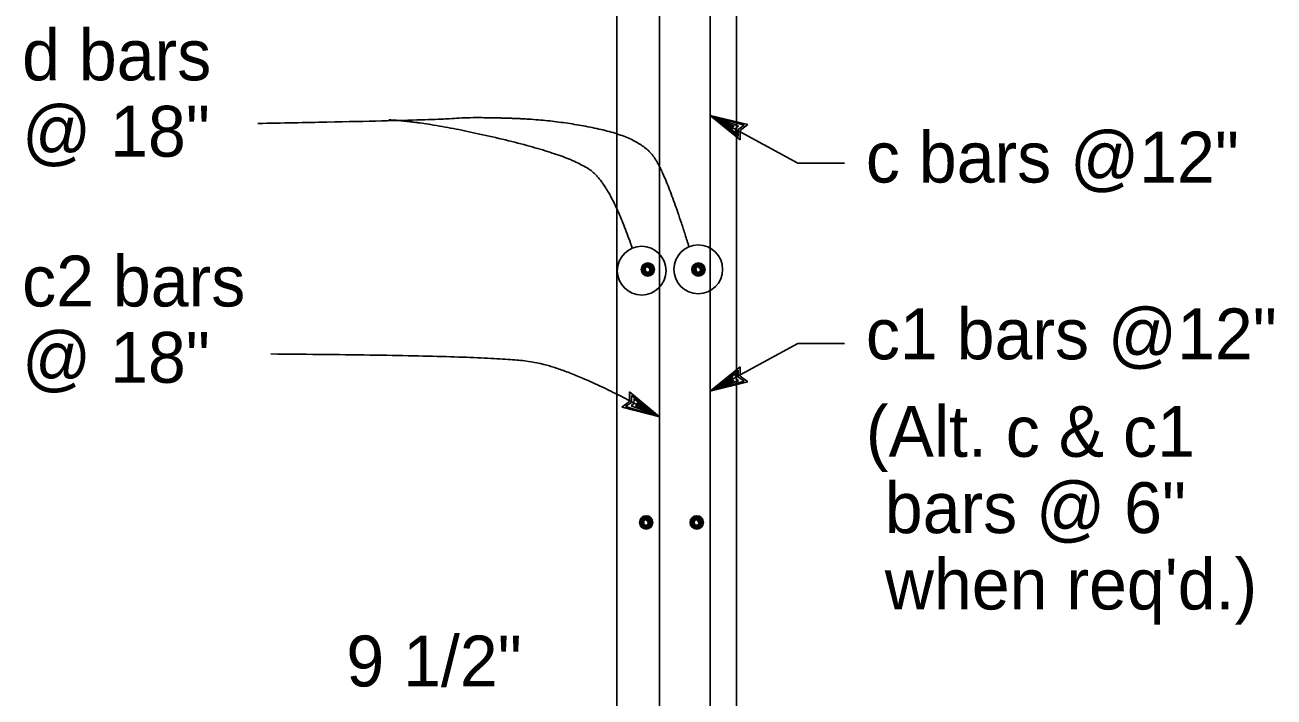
# Model space of a CAD drawing. Extents: x -0.08 to 2.83, y -0.03 to 1.92.
# Drawn here: x 1.6391 to 1.9587, y 0.4851 to 0.6571 of the extents above; entities that cross this region are included whole.
import ezdxf

# ---------------------------------------------------------------- set-up
doc = ezdxf.new("R2010")
doc.units = 0
for name, color, linetype in [('50', 7, 'Continuous'), ('51', 7, 'Continuous'), ('55', 7, 'Continuous'), ('57', 7, 'Continuous')]:
    doc.layers.add(name, color=color, linetype=linetype)

msp = doc.modelspace()

# ---------------------------------------------------------------- linework, layer by layer
at = {"layer": '50'}
for p, q in [((1.79058, 0.37752), (1.79058, 0.72906)), ((1.82123, 0.72906), (1.82123, 0.37752))]:
    msp.add_line(p, q, dxfattribs=at)
at = {"layer": '51'}
for p, q in [((1.80148, 0.72394), (1.80148, 0.4673)), ((1.81443, 0.72394), (1.81443, 0.50937)), ((1.81443, 0.50937), (1.81443, 0.46972))]:
    msp.add_line(p, q, dxfattribs=at)
for points in [[(1.7969, 0.59466), (1.79712, 0.59531), (1.79758, 0.5958), (1.79817, 0.59607), (1.79874, 0.59607), (1.79919, 0.59593), (1.79956, 0.59564), (1.79986, 0.59523), (1.8, 0.59483), (1.80005, 0.59428), (1.79993, 0.59376), (1.79966, 0.5934), (1.79924, 0.59308), (1.79874, 0.59291), (1.79812, 0.59291), (1.79763, 0.59316), (1.79727, 0.59346), (1.79707, 0.59379), (1.79694, 0.59419), (1.79695, 0.59457), (1.79709, 0.59496), (1.79728, 0.59534), (1.79758, 0.59566), (1.79786, 0.59586), (1.79813, 0.59596), (1.79841, 0.59598), (1.79879, 0.59598), (1.79911, 0.59586), (1.79937, 0.59564), (1.79959, 0.59545), (1.79979, 0.59515), (1.79989, 0.59477), (1.79993, 0.59438), (1.79989, 0.59405), (1.79976, 0.59367), (1.79961, 0.59348), (1.79934, 0.59329), (1.79909, 0.59313), (1.79879, 0.59304), (1.79844, 0.59299), (1.798, 0.59311), (1.79763, 0.59329), (1.79735, 0.59354), (1.79712, 0.59398), (1.79705, 0.59438), (1.79714, 0.59477), (1.79731, 0.59515), (1.79757, 0.59551), (1.79781, 0.59572), (1.7981, 0.59583), (1.79849, 0.59588), (1.79885, 0.5958), (1.79911, 0.59566), (1.79941, 0.59539), (1.79966, 0.59504), (1.79974, 0.59468), (1.79977, 0.59428), (1.79973, 0.59395), (1.79951, 0.59354), (1.79924, 0.59332), (1.79891, 0.59321), (1.79848, 0.59313), (1.79803, 0.59324), (1.79769, 0.5934), (1.79745, 0.59362), (1.79728, 0.59392), (1.7972, 0.59419), (1.7972, 0.59455), (1.79731, 0.59483), (1.79744, 0.59509), (1.7976, 0.59531), (1.79786, 0.59561), (1.79815, 0.59574), (1.79849, 0.59577), (1.79878, 0.59569), (1.79916, 0.59541), (1.79941, 0.59509), (1.79959, 0.59471), (1.79961, 0.5943), (1.79954, 0.594), (1.79949, 0.59379), (1.79924, 0.59348), (1.79901, 0.59337), (1.79861, 0.59324), (1.7982, 0.59332), (1.79781, 0.59348), (1.79754, 0.5937), (1.79737, 0.59403), (1.79729, 0.59433), (1.79737, 0.59468), (1.79758, 0.59506), (1.79778, 0.59536), (1.798, 0.59561), (1.79833, 0.59569), (1.79848, 0.59564), (1.79871, 0.59561), (1.79891, 0.59545), (1.79918, 0.59518), (1.79929, 0.59501), (1.79941, 0.59483), (1.79947, 0.59463)], [(1.79947, 0.59463), (1.79938, 0.59413), (1.79934, 0.59379), (1.79916, 0.59362), (1.79891, 0.59346), (1.79861, 0.5934), (1.79828, 0.5934), (1.79797, 0.59351), (1.79773, 0.5937), (1.79755, 0.59392), (1.79743, 0.59416), (1.79749, 0.59457), (1.79763, 0.59493), (1.79781, 0.59518), (1.79802, 0.59548), (1.7983, 0.59558), (1.79861, 0.59545), (1.79876, 0.59534), (1.79898, 0.59515), (1.79911, 0.59498), (1.79924, 0.59477), (1.79927, 0.59457), (1.79929, 0.59438), (1.79926, 0.59419), (1.79918, 0.59389), (1.79912, 0.59376), (1.79904, 0.59367), (1.79885, 0.59356), (1.79873, 0.59351), (1.79857, 0.59351), (1.79839, 0.59351), (1.79826, 0.59351), (1.7981, 0.59356), (1.79795, 0.59367), (1.79766, 0.59405), (1.79758, 0.59428), (1.7976, 0.59452), (1.79768, 0.59477), (1.79776, 0.59491), (1.79788, 0.59512), (1.798, 0.59523), (1.79815, 0.59536), (1.79831, 0.59541), (1.79859, 0.59534), (1.79867, 0.59528), (1.79879, 0.59515), (1.79891, 0.59501), (1.79901, 0.59488), (1.79906, 0.59473), (1.79913, 0.59463), (1.79918, 0.59449), (1.79919, 0.59441), (1.79913, 0.59424), (1.79911, 0.59413), (1.79906, 0.59403), (1.79898, 0.59389), (1.79888, 0.59376), (1.79878, 0.5937), (1.79859, 0.59365), (1.79844, 0.59365), (1.79828, 0.59365), (1.79815, 0.59372), (1.798, 0.59384), (1.79788, 0.59398), (1.79781, 0.59411), (1.79776, 0.59424), (1.79771, 0.59438), (1.79781, 0.59452), (1.79786, 0.59466), (1.79793, 0.59488), (1.79802, 0.59501), (1.79811, 0.59512), (1.79825, 0.59518), (1.79844, 0.59518), (1.79861, 0.59509), (1.79869, 0.59504), (1.79882, 0.59488), (1.79888, 0.59477), (1.79893, 0.59468), (1.79898, 0.59457), (1.79899, 0.59447), (1.79901, 0.59433), (1.79899, 0.59422), (1.79898, 0.59416), (1.79891, 0.59405), (1.79883, 0.594), (1.79879, 0.59395), (1.79876, 0.59389), (1.79871, 0.59384), (1.79861, 0.59381), (1.79852, 0.59381), (1.79839, 0.59384), (1.79828, 0.59384), (1.79817, 0.59389), (1.79807, 0.59395), (1.79797, 0.59403), (1.79793, 0.59411), (1.79792, 0.59422), (1.79788, 0.59435), (1.79786, 0.59444), (1.79792, 0.59455)], [(1.80984, 0.59466), (1.81006, 0.59531), (1.81052, 0.5958), (1.81111, 0.59607), (1.81168, 0.59607), (1.81213, 0.59593), (1.81251, 0.59564), (1.8128, 0.59523), (1.81295, 0.59483), (1.81299, 0.59428), (1.81287, 0.59376), (1.81261, 0.5934), (1.81218, 0.59308), (1.81168, 0.59291), (1.81107, 0.59291), (1.81058, 0.59316), (1.81021, 0.59346), (1.81001, 0.59379), (1.80988, 0.59419), (1.80989, 0.59457), (1.81004, 0.59496), (1.81022, 0.59534), (1.81052, 0.59566), (1.81081, 0.59586), (1.81108, 0.59596), (1.81136, 0.59598), (1.81173, 0.59598), (1.81205, 0.59586), (1.81231, 0.59564), (1.81253, 0.59545), (1.81273, 0.59515), (1.81284, 0.59477), (1.81287, 0.59438), (1.81283, 0.59405), (1.81271, 0.59367), (1.81256, 0.59348), (1.81228, 0.59329), (1.81204, 0.59313), (1.81173, 0.59304), (1.81138, 0.59299), (1.81094, 0.59311), (1.81058, 0.59329), (1.8103, 0.59354), (1.81006, 0.59398), (1.80999, 0.59438), (1.81009, 0.59477), (1.81025, 0.59515), (1.81051, 0.59551), (1.81074, 0.59572), (1.81104, 0.59583), (1.81144, 0.59588), (1.81179, 0.5958), (1.81205, 0.59566), (1.81236, 0.59539), (1.81259, 0.59504), (1.81269, 0.59468), (1.81272, 0.59428), (1.81268, 0.59395), (1.81246, 0.59354), (1.81218, 0.59332), (1.81186, 0.59321), (1.81142, 0.59313), (1.81098, 0.59324), (1.81064, 0.5934), (1.8104, 0.59362), (1.81022, 0.59392), (1.81014, 0.59419), (1.81014, 0.59455), (1.81025, 0.59483), (1.81039, 0.59509), (1.81055, 0.59531), (1.81081, 0.59561), (1.8111, 0.59574), (1.81144, 0.59577), (1.81173, 0.59569), (1.8121, 0.59541), (1.81236, 0.59509), (1.81253, 0.59471), (1.81256, 0.5943), (1.81249, 0.594), (1.81243, 0.59379), (1.81219, 0.59348), (1.81195, 0.59337), (1.81156, 0.59324), (1.81114, 0.59332), (1.81076, 0.59348), (1.81049, 0.5937), (1.81031, 0.59403), (1.81024, 0.59433), (1.81032, 0.59468), (1.81052, 0.59506), (1.81073, 0.59536), (1.81094, 0.59561), (1.81127, 0.59569), (1.81142, 0.59564), (1.81166, 0.59561), (1.81184, 0.59545), (1.81212, 0.59518), (1.81224, 0.59501), (1.81236, 0.59483), (1.81242, 0.59463)], [(1.81242, 0.59463), (1.81233, 0.59413), (1.81228, 0.59379), (1.8121, 0.59362), (1.81186, 0.59346), (1.81156, 0.5934), (1.81123, 0.5934), (1.81093, 0.59351), (1.81067, 0.5937), (1.8105, 0.59392), (1.81037, 0.59416), (1.81043, 0.59457), (1.81058, 0.59493), (1.81076, 0.59518), (1.81096, 0.59548), (1.81125, 0.59558), (1.81156, 0.59545), (1.8117, 0.59534), (1.81191, 0.59515), (1.81205, 0.59498), (1.81218, 0.59477), (1.81221, 0.59457), (1.81224, 0.59438), (1.8122, 0.59419), (1.81212, 0.59389), (1.81206, 0.59376), (1.81198, 0.59367), (1.81179, 0.59356), (1.81168, 0.59351), (1.81152, 0.59351), (1.81133, 0.59351), (1.8112, 0.59351), (1.81104, 0.59356), (1.81089, 0.59367), (1.81061, 0.59405), (1.81052, 0.59428), (1.81054, 0.59452), (1.81061, 0.59477), (1.8107, 0.59491), (1.81083, 0.59512), (1.81094, 0.59523), (1.8111, 0.59536), (1.81126, 0.59541), (1.81153, 0.59534), (1.81162, 0.59528), (1.81173, 0.59515), (1.81186, 0.59501), (1.81195, 0.59488), (1.81201, 0.59473), (1.81208, 0.59463), (1.81212, 0.59449), (1.81213, 0.59441), (1.81208, 0.59424), (1.81205, 0.59413), (1.81201, 0.59403), (1.81193, 0.59389), (1.81183, 0.59376), (1.81173, 0.5937), (1.81153, 0.59365), (1.81138, 0.59365), (1.81123, 0.59365), (1.8111, 0.59372), (1.81094, 0.59384), (1.81083, 0.59398), (1.81076, 0.59411), (1.8107, 0.59424), (1.81066, 0.59438), (1.81074, 0.59452), (1.81079, 0.59466), (1.81088, 0.59488), (1.81096, 0.59501), (1.81105, 0.59512), (1.81119, 0.59518), (1.81138, 0.59518), (1.81156, 0.59509), (1.81163, 0.59504), (1.81176, 0.59488), (1.81183, 0.59477), (1.81188, 0.59468), (1.81191, 0.59457), (1.81194, 0.59447), (1.81195, 0.59433), (1.81194, 0.59422), (1.81193, 0.59416), (1.81184, 0.59405), (1.81178, 0.594), (1.81173, 0.59395), (1.81171, 0.59389), (1.81166, 0.59384), (1.81156, 0.59381), (1.81147, 0.59381), (1.81133, 0.59384), (1.81122, 0.59384), (1.81111, 0.59389), (1.81102, 0.59395), (1.81093, 0.59403), (1.81088, 0.59411), (1.81087, 0.59422), (1.81083, 0.59435), (1.81081, 0.59444), (1.81087, 0.59455)], [(1.79648, 0.52993), (1.79669, 0.53059), (1.79716, 0.53108), (1.79775, 0.53135), (1.79831, 0.53135), (1.79876, 0.53121), (1.79913, 0.53092), (1.79944, 0.53051), (1.79959, 0.5301), (1.79962, 0.52955), (1.7995, 0.52904), (1.79924, 0.52868), (1.79881, 0.52836), (1.79831, 0.52819), (1.7977, 0.52819), (1.79721, 0.52843), (1.79684, 0.52874), (1.79664, 0.52907), (1.79652, 0.52947), (1.79654, 0.52986), (1.79667, 0.53023), (1.79686, 0.53061), (1.79716, 0.53094), (1.79744, 0.53113), (1.79771, 0.53124), (1.79799, 0.53127), (1.79837, 0.53127), (1.79869, 0.53113), (1.79894, 0.53092), (1.79916, 0.53072), (1.79937, 0.53043), (1.79947, 0.53004), (1.7995, 0.52966), (1.79946, 0.52933), (1.79934, 0.52895), (1.79919, 0.52876), (1.79891, 0.52857), (1.79867, 0.52841), (1.79837, 0.52832), (1.79802, 0.52827), (1.79758, 0.52838), (1.79721, 0.52857), (1.79692, 0.52882), (1.79669, 0.52925), (1.79663, 0.52966), (1.79672, 0.53004), (1.79689, 0.53043), (1.79714, 0.53077), (1.79737, 0.53099), (1.79768, 0.53111), (1.79807, 0.53116), (1.79843, 0.53108), (1.79869, 0.53094), (1.79898, 0.53067), (1.79924, 0.53031), (1.79932, 0.52996), (1.79935, 0.52955), (1.79931, 0.52923), (1.79909, 0.52882), (1.79881, 0.5286), (1.79849, 0.52848), (1.79806, 0.52841), (1.7976, 0.52852), (1.79727, 0.52868), (1.79703, 0.5289), (1.79686, 0.5292), (1.79677, 0.52947), (1.79677, 0.52982), (1.79689, 0.5301), (1.79702, 0.53037), (1.79719, 0.53059), (1.79744, 0.53089), (1.79773, 0.53102), (1.79807, 0.53105), (1.79836, 0.53097), (1.79874, 0.5307), (1.79898, 0.53037), (1.79916, 0.52999), (1.79919, 0.52958), (1.79912, 0.52928), (1.79906, 0.52907), (1.79882, 0.52876), (1.79859, 0.52865), (1.7982, 0.52852), (1.79777, 0.5286), (1.79739, 0.52876), (1.79712, 0.52897), (1.79694, 0.52931), (1.79687, 0.5296), (1.79695, 0.52996), (1.79716, 0.53034), (1.79737, 0.53064), (1.79758, 0.53089), (1.79791, 0.53097), (1.79806, 0.53092), (1.79828, 0.53089), (1.79848, 0.53072), (1.79876, 0.53045), (1.79888, 0.53028), (1.79898, 0.5301), (1.79906, 0.52991)], [(1.79906, 0.52991), (1.79896, 0.52942), (1.79891, 0.52907), (1.79874, 0.5289), (1.79849, 0.52874), (1.7982, 0.52868), (1.79786, 0.52868), (1.79755, 0.52879), (1.79731, 0.52897), (1.79713, 0.5292), (1.79701, 0.52944), (1.79707, 0.52986), (1.79721, 0.53021), (1.79739, 0.53045), (1.7976, 0.53075), (1.79788, 0.53087), (1.7982, 0.53072), (1.79833, 0.53061), (1.79854, 0.53043), (1.79869, 0.53026), (1.79881, 0.53004), (1.79885, 0.52986), (1.79888, 0.52966), (1.79883, 0.52947), (1.79876, 0.52917), (1.7987, 0.52904), (1.79861, 0.52895), (1.79843, 0.52885), (1.7983, 0.52879), (1.79815, 0.52879), (1.79796, 0.52879), (1.79784, 0.52879), (1.79768, 0.52885), (1.79752, 0.52895), (1.79724, 0.52933), (1.79716, 0.52955), (1.79718, 0.5298), (1.79725, 0.53004), (1.79734, 0.53017), (1.79745, 0.5304), (1.79758, 0.53051), (1.79773, 0.53064), (1.79789, 0.5307), (1.79817, 0.53061), (1.79825, 0.53056), (1.79837, 0.53043), (1.79849, 0.53028), (1.79859, 0.53015), (1.79864, 0.53002), (1.79871, 0.52991), (1.79876, 0.52977), (1.79876, 0.52969), (1.79871, 0.52952), (1.79869, 0.52942), (1.79864, 0.52931), (1.79856, 0.52917), (1.79846, 0.52904), (1.79836, 0.52897), (1.79817, 0.52892), (1.79802, 0.52892), (1.79786, 0.52892), (1.79773, 0.52901), (1.79758, 0.52912), (1.79745, 0.52925), (1.79739, 0.52939), (1.79734, 0.52952), (1.79729, 0.52966), (1.79737, 0.5298), (1.79743, 0.52993), (1.79752, 0.53015), (1.7976, 0.53028), (1.79769, 0.5304), (1.79783, 0.53045), (1.79802, 0.53045), (1.7982, 0.53037), (1.79826, 0.53031), (1.7984, 0.53015), (1.79846, 0.53004), (1.79851, 0.52996), (1.79854, 0.52986), (1.79857, 0.52975), (1.79859, 0.5296), (1.79857, 0.5295), (1.79856, 0.52944), (1.79848, 0.52933), (1.79841, 0.52928), (1.79837, 0.52923), (1.79834, 0.52917), (1.79828, 0.52912), (1.7982, 0.52909), (1.7981, 0.52909), (1.79796, 0.52912), (1.79786, 0.52912), (1.79775, 0.52917), (1.79764, 0.52923), (1.79755, 0.52931), (1.79752, 0.52939), (1.7975, 0.5295), (1.79745, 0.52963), (1.79744, 0.52972), (1.7975, 0.52982)], [(1.80942, 0.52993), (1.80964, 0.53059), (1.8101, 0.53108), (1.81069, 0.53135), (1.81126, 0.53135), (1.81171, 0.53121), (1.81208, 0.53092), (1.81238, 0.53051), (1.81253, 0.5301), (1.81257, 0.52955), (1.81244, 0.52904), (1.81219, 0.52868), (1.81175, 0.52836), (1.81126, 0.52819), (1.81064, 0.52819), (1.81016, 0.52843), (1.80979, 0.52874), (1.80959, 0.52907), (1.80946, 0.52947), (1.80948, 0.52986), (1.80962, 0.53023), (1.80981, 0.53061), (1.8101, 0.53094), (1.81039, 0.53113), (1.81066, 0.53124), (1.81094, 0.53127), (1.81132, 0.53127), (1.81163, 0.53113), (1.81189, 0.53092), (1.8121, 0.53072), (1.81231, 0.53043), (1.81242, 0.53004), (1.81244, 0.52966), (1.81241, 0.52933), (1.81228, 0.52895), (1.81213, 0.52876), (1.81186, 0.52857), (1.81162, 0.52841), (1.81132, 0.52832), (1.81096, 0.52827), (1.81052, 0.52838), (1.81016, 0.52857), (1.80988, 0.52882), (1.80964, 0.52925), (1.80957, 0.52966), (1.80967, 0.53004), (1.80983, 0.53043), (1.81009, 0.53077), (1.81032, 0.53099), (1.81061, 0.53111), (1.81102, 0.53116), (1.81137, 0.53108), (1.81163, 0.53094), (1.81193, 0.53067), (1.81218, 0.53031), (1.81226, 0.52996), (1.8123, 0.52955), (1.81226, 0.52923), (1.81204, 0.52882), (1.81175, 0.5286), (1.81144, 0.52848), (1.811, 0.52841), (1.81055, 0.52852), (1.81021, 0.52868), (1.80998, 0.5289), (1.80981, 0.5292), (1.80972, 0.52947), (1.80972, 0.52982), (1.80983, 0.5301), (1.80996, 0.53037), (1.81013, 0.53059), (1.81039, 0.53089), (1.81067, 0.53102), (1.81102, 0.53105), (1.81131, 0.53097), (1.81168, 0.5307), (1.81193, 0.53037), (1.8121, 0.52999), (1.81213, 0.52958), (1.81206, 0.52928), (1.81201, 0.52907), (1.81176, 0.52876), (1.81153, 0.52865), (1.81114, 0.52852), (1.81072, 0.5286), (1.81033, 0.52876), (1.81006, 0.52897), (1.80988, 0.52931), (1.80982, 0.5296), (1.80989, 0.52996), (1.8101, 0.53034), (1.81031, 0.53064), (1.81052, 0.53089), (1.81085, 0.53097), (1.811, 0.53092), (1.81123, 0.53089), (1.81142, 0.53072), (1.8117, 0.53045), (1.81182, 0.53028), (1.81193, 0.5301), (1.81199, 0.52991)], [(1.81199, 0.52991), (1.8119, 0.52942), (1.81186, 0.52907), (1.81168, 0.5289), (1.81144, 0.52874), (1.81114, 0.52868), (1.81081, 0.52868), (1.8105, 0.52879), (1.81025, 0.52897), (1.81008, 0.5292), (1.80996, 0.52944), (1.81001, 0.52986), (1.81016, 0.53021), (1.81033, 0.53045), (1.81054, 0.53075), (1.81083, 0.53087), (1.81114, 0.53072), (1.81127, 0.53061), (1.81149, 0.53043), (1.81163, 0.53026), (1.81175, 0.53004), (1.81179, 0.52986), (1.81182, 0.52966), (1.81178, 0.52947), (1.8117, 0.52917), (1.81164, 0.52904), (1.81156, 0.52895), (1.81137, 0.52885), (1.81125, 0.52879), (1.8111, 0.52879), (1.8109, 0.52879), (1.81079, 0.52879), (1.81061, 0.52885), (1.81047, 0.52895), (1.81019, 0.52933), (1.8101, 0.52955), (1.81011, 0.5298), (1.8102, 0.53004), (1.81028, 0.53017), (1.8104, 0.5304), (1.81052, 0.53051), (1.81067, 0.53064), (1.81084, 0.5307), (1.81111, 0.53061), (1.81119, 0.53056), (1.81132, 0.53043), (1.81144, 0.53028), (1.81153, 0.53015), (1.81158, 0.53002), (1.81166, 0.52991), (1.8117, 0.52977), (1.81171, 0.52969), (1.81166, 0.52952), (1.81163, 0.52942), (1.81158, 0.52931), (1.81151, 0.52917), (1.81141, 0.52904), (1.81131, 0.52897), (1.81111, 0.52892), (1.81096, 0.52892), (1.81081, 0.52892), (1.81067, 0.52901), (1.81052, 0.52912), (1.8104, 0.52925), (1.81033, 0.52939), (1.81028, 0.52952), (1.81024, 0.52966), (1.81032, 0.5298), (1.81037, 0.52993), (1.81046, 0.53015), (1.81054, 0.53028), (1.81064, 0.5304), (1.81077, 0.53045), (1.81096, 0.53045), (1.81114, 0.53037), (1.8112, 0.53031), (1.81134, 0.53015), (1.81141, 0.53004), (1.81145, 0.52996), (1.81149, 0.52986), (1.81152, 0.52975), (1.81153, 0.5296), (1.81152, 0.5295), (1.81151, 0.52944), (1.81142, 0.52933), (1.81136, 0.52928), (1.81132, 0.52923), (1.81129, 0.52917), (1.81123, 0.52912), (1.81114, 0.52909), (1.81104, 0.52909), (1.8109, 0.52912), (1.81079, 0.52912), (1.81069, 0.52917), (1.81059, 0.52923), (1.8105, 0.52931), (1.81046, 0.52939), (1.81044, 0.5295), (1.8104, 0.52963), (1.81039, 0.52972), (1.81044, 0.52982)]]:
    msp.add_lwpolyline(points, dxfattribs=at)
for centre in [(1.79851, 0.5945), (1.81145, 0.5945), (1.79809, 0.52978), (1.81103, 0.52978)]:
    msp.add_circle(centre, 0.0017, dxfattribs=at)
at = {"layer": '55'}
for p, q in [((1.81443, 0.63394), (1.83687, 0.62172)), ((1.81443, 0.63394), (1.82409, 0.63158)), ((1.82215, 0.62767), (1.81443, 0.63394)), ((1.81443, 0.63394), (1.82315, 0.63141)), ((1.82164, 0.62854), (1.81556, 0.63338)), ((1.81556, 0.63338), (1.82174, 0.63125)), ((1.82098, 0.62943), (1.81714, 0.63244)), ((1.81714, 0.63244), (1.8206, 0.63119)), ((1.82023, 0.63044), (1.81871, 0.63166)), ((1.81871, 0.63166), (1.81953, 0.63125)), ((1.8206, 0.63119), (1.81982, 0.63119)), ((1.81982, 0.63119), (1.82023, 0.63044)), ((1.82104, 0.63065), (1.82098, 0.62943)), ((1.82174, 0.63125), (1.82104, 0.63065)), ((1.82315, 0.63141), (1.82161, 0.63036)), ((1.82161, 0.63036), (1.82164, 0.62854)), ((1.82217, 0.63008), (1.82215, 0.62767)), ((1.82409, 0.63158), (1.82217, 0.63008)), ((1.83687, 0.62172), (1.84882, 0.62172)), ((1.81443, 0.56336), (1.83687, 0.57558)), ((1.83687, 0.57558), (1.84882, 0.57558)), ((1.82215, 0.56963), (1.81443, 0.56336)), ((1.82217, 0.56722), (1.82215, 0.56963)), ((1.81443, 0.56336), (1.82315, 0.56589)), ((1.81443, 0.56336), (1.82409, 0.56573)), ((1.82164, 0.56876), (1.81556, 0.56393)), ((1.81556, 0.56393), (1.82174, 0.56605)), ((1.82098, 0.56788), (1.81714, 0.56486)), ((1.81714, 0.56486), (1.8206, 0.56611)), ((1.82023, 0.56686), (1.81871, 0.56564)), ((1.81871, 0.56564), (1.81953, 0.56605)), ((1.81982, 0.56611), (1.82023, 0.56686)), ((1.8206, 0.56611), (1.81982, 0.56611)), ((1.82104, 0.56665), (1.82098, 0.56788)), ((1.82174, 0.56605), (1.82104, 0.56665)), ((1.82161, 0.56694), (1.82164, 0.56876)), ((1.82315, 0.56589), (1.82161, 0.56694)), ((1.82409, 0.56573), (1.82217, 0.56722)), ((1.79378, 0.56075), (1.79382, 0.56317)), ((1.79382, 0.56317), (1.80148, 0.55681)), ((1.79184, 0.55928), (1.79378, 0.56075)), ((1.80148, 0.55681), (1.79184, 0.55928)), ((1.79278, 0.55943), (1.79434, 0.56046)), ((1.80148, 0.55681), (1.79278, 0.55943)), ((1.7942, 0.55958), (1.7949, 0.56018)), ((1.80035, 0.55739), (1.7942, 0.55958)), ((1.79434, 0.56046), (1.79432, 0.56229)), ((1.79432, 0.56229), (1.80035, 0.55739)), ((1.7949, 0.56018), (1.79497, 0.5614)), ((1.79497, 0.5614), (1.79878, 0.55834)), ((1.79878, 0.55834), (1.79533, 0.55963)), ((1.79533, 0.55963), (1.79612, 0.55962)), ((1.79612, 0.55962), (1.79572, 0.56038)), ((1.79572, 0.56038), (1.79722, 0.55914)), ((1.79722, 0.55914), (1.7964, 0.55956))]:
    msp.add_line(p, q, dxfattribs=at)
for centre in [(1.79693, 0.5942), (1.8114, 0.59453)]:
    msp.add_circle(centre, 0.00624, dxfattribs=at)
for points in [[(1.80904, 0.60027), (1.80351, 0.6182), (1.79686, 0.62802), (1.77583, 0.63271), (1.7537, 0.63357), (1.74374, 0.63271), (1.69872, 0.63186)], [(1.79451, 0.59997), (1.78916, 0.61578), (1.77893, 0.62369), (1.74193, 0.63238), (1.7322, 0.63278)], [(1.80148, 0.55681), (1.77889, 0.56942), (1.75769, 0.5725), (1.70203, 0.57288)]]:
    msp.add_open_spline(points, degree=2, dxfattribs=at)

# ---------------------------------------------------------------- texts
at = {"layer": '57'}
for s, height, p in [('d bars', 0.013021, (1.63841, 0.6429)), ('@ 18"', 0.013021, (1.63841, 0.62337)), ('c bars @12"', 0.0130208, (1.8543, 0.61675)), ('c2 bars', 0.013021, (1.63841, 0.58504)), ('c1 bars @12"', 0.0130208, (1.8543, 0.57152)), ('@ 18"', 0.013021, (1.63841, 0.56551)), ('(Alt. c & c1', 0.0130208, (1.8543, 0.54657)), (' bars @ 6"', 0.013021, (1.8543, 0.52704)), (" when req'd.)", 0.0130208, (1.8543, 0.50751)), ('9 1/2"', 0.013021, (1.72136, 0.48781))]:
    msp.add_text(s, height=height, dxfattribs=at).set_placement(p)

doc.saveas('drawing.dxf')
